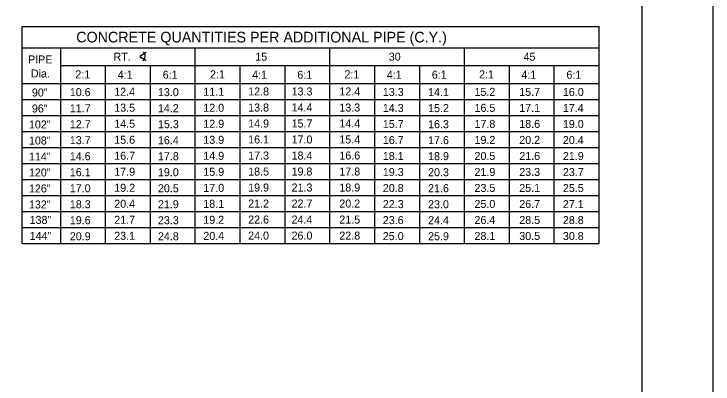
# Model space of a CAD drawing. Extents: x -0.08 to 2.83, y -0.03 to 1.92.
# Drawn here: x 1.811 to 2.833, y 0.542 to 1.083 of the extents above; entities that cross this region are included whole.
import ezdxf

# ---------------------------------------------------------------- set-up
doc = ezdxf.new("R2010")
doc.units = 0
doc.layers.add('57', color=7, linetype='Continuous')
doc.layers.add('63', color=7, linetype='Continuous')

msp = doc.modelspace()

# ---------------------------------------------------------------- linework, layer by layer
at = {"layer": '57'}
for p, q in [((1.8229, 0.7473), (1.8229, 1.065)), ((1.8229, 1.065), (2.6667, 1.065)), ((2.6667, 0.7473), (2.6667, 1.065)), ((1.8229, 1.0338), (2.6667, 1.0338)), ((1.8792, 0.7473), (1.8792, 1.0338)), ((2.076, 0.7473), (2.076, 1.0338)), ((2.2729, 0.7473), (2.2729, 1.0338)), ((2.4698, 0.7473), (2.4698, 1.0338)), ((2.0041, 1.027), (1.9949, 1.0213)), ((1.9949, 1.0213), (2.0041, 1.0151)), ((1.8792, 1.0078), (2.6667, 1.0078)), ((1.9448, 0.7473), (1.9448, 1.0078)), ((2.0104, 0.7473), (2.0104, 1.0078)), ((2.1417, 0.7473), (2.1417, 1.0078)), ((2.2073, 0.7473), (2.2073, 1.0078)), ((2.3386, 0.7473), (2.3386, 1.0078)), ((2.4042, 0.7473), (2.4042, 1.0078)), ((2.5354, 0.7473), (2.5354, 1.0078)), ((2.6011, 0.7473), (2.6011, 1.0078)), ((1.8229, 0.9817), (2.6667, 0.9817)), ((1.8229, 0.9583), (2.6667, 0.9583)), ((2.4697, 0.9583), (2.6667, 0.9583)), ((2.4697, 0.9583), (2.6667, 0.9583)), ((1.8229, 0.9348), (2.6667, 0.9348)), ((2.4697, 0.9348), (2.6667, 0.9348)), ((2.4697, 0.9348), (2.6667, 0.9348)), ((1.8229, 0.9114), (2.6667, 0.9114)), ((2.4697, 0.9114), (2.6667, 0.9114)), ((2.4697, 0.9114), (2.6667, 0.9114)), ((1.8229, 0.888), (2.6667, 0.888)), ((2.4697, 0.888), (2.6667, 0.888)), ((2.4697, 0.888), (2.6667, 0.888)), ((1.8229, 0.8645), (2.6667, 0.8645)), ((2.4697, 0.8645), (2.6667, 0.8645)), ((2.4697, 0.8645), (2.6667, 0.8645)), ((1.8229, 0.8411), (2.6667, 0.8411)), ((2.4697, 0.8411), (2.6667, 0.8411)), ((2.4697, 0.8411), (2.6667, 0.8411)), ((1.8229, 0.8176), (2.6667, 0.8176)), ((2.4697, 0.8176), (2.6667, 0.8176)), ((2.4697, 0.8176), (2.6667, 0.8176)), ((1.8229, 0.7942), (2.6667, 0.7942)), ((2.4697, 0.7942), (2.6667, 0.7942)), ((2.4697, 0.7942), (2.6667, 0.7942)), ((1.8229, 0.7708), (2.6667, 0.7708)), ((2.4697, 0.7708), (2.6667, 0.7708)), ((2.4697, 0.7708), (2.6667, 0.7708)), ((1.8229, 0.7473), (2.6667, 0.7473)), ((2.4697, 0.7473), (2.6667, 0.7473)), ((2.4697, 0.7473), (2.6667, 0.7473))]:
    msp.add_line(p, q, dxfattribs=at)
msp.add_arc((1.9944, 1.0216), 0.00814, 306.1214, 46.4199, dxfattribs=at)
at = {"layer": '63'}
msp.add_line((2.8333, 1.8333), (2.8333, 0), dxfattribs=at)
msp.add_lwpolyline([(0.1667, 0.0624), (0.1667, 1.7708), (2.7292, 1.7708), (2.7292, 0.1041), (2.5625, 0.1041), (2.5625, 0.1458), (2.0739, 0.1458), (2.0739, 0.0624)], close=True, dxfattribs=at)

# ---------------------------------------------------------------- texts
at = {"layer": '57'}
for s, height, p in [('CONCRETE QUANTITIES PER ADDITIONAL PIPE (C.Y.)', 0.015625, (1.9018, 1.0417)), ('PIPE', 0.01171, (1.8313, 1.011)), ('RT.', 0.01171, (1.9563, 1.015)), ('15', 0.01171, (2.1637, 1.015)), ('30', 0.01171, (2.359, 1.015)), ('45', 0.01171, (2.5561, 1.015)), ('Dia.', 0.01171, (1.8354, 0.9904)), ('2:1', 0.0117, (1.9005, 0.9891)), ('2:1', 0.0117, (1.9005, 0.9891)), ('2:1', 0.0117, (1.9005, 0.9891)), ('4:1', 0.0117, (1.9624, 0.9886)), ('4:1', 0.0117, (1.9624, 0.9886)), ('4:1', 0.0117, (1.9624, 0.9886)), ('6:1', 0.0117, (2.0283, 0.9886)), ('6:1', 0.0117, (2.0283, 0.9886)), ('6:1', 0.0117, (2.0283, 0.9886)), ('2:1', 0.0117, (2.0974, 0.9891)), ('2:1', 0.0117, (2.0974, 0.9891)), ('2:1', 0.0117, (2.0974, 0.9891)), ('4:1', 0.0117, (2.1592, 0.9886)), ('4:1', 0.0117, (2.1592, 0.9886)), ('4:1', 0.0117, (2.1592, 0.9886)), ('6:1', 0.0117, (2.2252, 0.9886)), ('6:1', 0.0117, (2.2252, 0.9886)), ('6:1', 0.0117, (2.2252, 0.9886)), ('2:1', 0.0117, (2.2942, 0.9891)), ('2:1', 0.0117, (2.2942, 0.9891)), ('2:1', 0.0117, (2.2942, 0.9891)), ('4:1', 0.0117, (2.3561, 0.9886)), ('4:1', 0.0117, (2.3561, 0.9886)), ('4:1', 0.0117, (2.3561, 0.9886)), ('6:1', 0.0117, (2.422, 0.9886)), ('6:1', 0.0117, (2.422, 0.9886)), ('6:1', 0.0117, (2.422, 0.9886)), ('2:1', 0.0117, (2.4911, 0.9891)), ('2:1', 0.0117, (2.4911, 0.9891)), ('2:1', 0.0117, (2.4911, 0.9891)), ('4:1', 0.0117, (2.553, 0.9886)), ('4:1', 0.0117, (2.553, 0.9886)), ('4:1', 0.0117, (2.553, 0.9886)), ('6:1', 0.0117, (2.6189, 0.9886)), ('6:1', 0.0117, (2.6189, 0.9886)), ('6:1', 0.0117, (2.6189, 0.9886)), (' 90"', 0.0117, (1.8326, 0.9626)), ('10.6', 0.01171, (1.8924, 0.9631)), ('12.4', 0.01171, (1.9574, 0.9637)), ('13.0', 0.01171, (2.0213, 0.9631)), ('11.1', 0.01171, (2.0877, 0.9637)), ('12.8', 0.01171, (2.1533, 0.9641)), ('13.3', 0.01171, (2.2168, 0.9641)), ('12.4', 0.01171, (2.2867, 0.9641)), ('13.3', 0.01171, (2.3503, 0.9633)), ('14.1', 0.01171, (2.4165, 0.9631)), ('15.2', 0.01171, (2.4844, 0.9635)), ('15.7', 0.01171, (2.5499, 0.9635)), ('16.0', 0.01171, (2.6137, 0.9633)), ('11.7', 0.01171, (1.8924, 0.9396)), ('13.5', 0.01171, (1.9574, 0.9403)), ('14.2', 0.01171, (2.0213, 0.9396)), ('12.0', 0.01171, (2.0877, 0.9402)), ('13.8', 0.01171, (2.1533, 0.9406)), ('14.4', 0.01171, (2.2168, 0.9407)), ('13.3', 0.01171, (2.2867, 0.9406)), ('14.3', 0.01171, (2.3503, 0.9399)), ('15.2', 0.01171, (2.4165, 0.9397)), ('16.5', 0.01171, (2.4844, 0.9401)), ('17.1', 0.01171, (2.5499, 0.9401)), ('17.4', 0.01171, (2.6137, 0.9399)), (' 96"', 0.0117, (1.8326, 0.9392)), ('102"', 0.0117, (1.8326, 0.9158)), ('12.7', 0.01171, (1.8924, 0.9162)), ('14.5', 0.01171, (1.9574, 0.9169)), ('15.3', 0.01171, (2.0213, 0.9162)), ('12.9', 0.01171, (2.0877, 0.9168)), ('14.9', 0.01171, (2.1533, 0.9172)), ('15.7', 0.01171, (2.2168, 0.9172)), ('14.4', 0.01171, (2.2867, 0.9172)), ('15.7', 0.01171, (2.3503, 0.9164)), ('16.3', 0.01171, (2.4165, 0.9162)), ('17.8', 0.01171, (2.4844, 0.9166)), ('18.6', 0.01171, (2.5499, 0.9166)), ('19.0', 0.01171, (2.6137, 0.9164)), ('108"', 0.0117, (1.8326, 0.8923)), ('13.7', 0.01171, (1.8924, 0.8928)), ('15.6', 0.01171, (1.9574, 0.8934)), ('16.4', 0.01171, (2.0213, 0.8927)), ('13.9', 0.01171, (2.0877, 0.8933)), ('16.1', 0.01171, (2.1533, 0.8938)), ('17.0', 0.01171, (2.2168, 0.8938)), ('15.4', 0.01171, (2.2867, 0.8938)), ('16.7', 0.01171, (2.3503, 0.893)), ('17.6', 0.01171, (2.4165, 0.8928)), ('19.2', 0.01171, (2.4844, 0.8932)), ('20.2', 0.01171, (2.5499, 0.8932)), ('20.4', 0.01171, (2.6137, 0.893)), ('114"', 0.0117, (1.8326, 0.8689)), ('14.6', 0.01171, (1.8924, 0.8693)), ('16.7', 0.01171, (1.9574, 0.87)), ('17.8', 0.01171, (2.0213, 0.8693)), ('14.9', 0.01171, (2.0877, 0.8699)), ('17.3', 0.01171, (2.1533, 0.8703)), ('18.4', 0.01171, (2.2168, 0.8703)), ('16.6', 0.01171, (2.2867, 0.8703)), ('18.1', 0.01171, (2.3503, 0.8696)), ('18.9', 0.01171, (2.4165, 0.8694)), ('20.5', 0.01171, (2.4844, 0.8697)), ('21.6', 0.01171, (2.5499, 0.8697)), ('21.9', 0.01171, (2.6137, 0.8696)), ('120"', 0.0117, (1.8326, 0.8455)), ('16.1', 0.01171, (1.8924, 0.8459)), ('17.9', 0.01171, (1.9574, 0.8466)), ('19.0', 0.01171, (2.0213, 0.8459)), ('15.9', 0.01171, (2.0877, 0.8465)), ('18.5', 0.01171, (2.1533, 0.8469)), ('19.8', 0.01171, (2.2168, 0.8469)), ('17.8', 0.01171, (2.2867, 0.8469)), ('19.3', 0.01171, (2.3503, 0.8461)), ('20.3', 0.01171, (2.4165, 0.8459)), ('21.9', 0.01171, (2.4844, 0.8463)), ('23.3', 0.01171, (2.5499, 0.8463)), ('23.7', 0.01171, (2.6137, 0.8461)), ('126"', 0.0117, (1.8326, 0.8221)), ('17.0', 0.01171, (1.8924, 0.8224)), ('19.2', 0.01171, (1.9574, 0.8231)), ('20.5', 0.01171, (2.0213, 0.8224)), ('17.0', 0.01171, (2.0877, 0.823)), ('19.9', 0.01171, (2.1533, 0.8235)), ('21.3', 0.01171, (2.2168, 0.8235)), ('18.9', 0.01171, (2.2867, 0.8235)), ('20.8', 0.01171, (2.3503, 0.8227)), ('21.6', 0.01171, (2.4165, 0.8225)), ('23.5', 0.01171, (2.4844, 0.8229)), ('25.1', 0.01171, (2.5499, 0.8229)), ('25.5', 0.01171, (2.6137, 0.8227)), ('132"', 0.0117, (1.8326, 0.7987)), ('18.3', 0.01171, (1.8924, 0.799)), ('20.4', 0.01171, (1.9574, 0.7997)), ('21.9', 0.01171, (2.0213, 0.799)), ('18.1', 0.01171, (2.0877, 0.7996)), ('21.2', 0.01171, (2.1533, 0.8)), ('22.7', 0.01171, (2.2168, 0.8)), ('20.2', 0.01171, (2.2867, 0.8)), ('22.3', 0.01171, (2.3503, 0.7992)), ('23.0', 0.01171, (2.4165, 0.799)), ('25.0', 0.01171, (2.4844, 0.7994)), ('26.7', 0.01171, (2.5499, 0.7994)), ('27.1', 0.01171, (2.6137, 0.7992)), ('138"', 0.0117, (1.8336, 0.7761)), ('19.6', 0.01171, (1.8924, 0.7756)), ('21.7', 0.01171, (1.9574, 0.7762)), ('23.3', 0.01171, (2.0213, 0.7756)), ('19.2', 0.01171, (2.0877, 0.7762)), ('22.6', 0.01171, (2.1533, 0.7766)), ('24.4', 0.01171, (2.2168, 0.7766)), ('21.5', 0.01171, (2.2867, 0.7766)), ('23.6', 0.01171, (2.3503, 0.7758)), ('24.4', 0.01171, (2.4165, 0.7756)), ('26.4', 0.01171, (2.4844, 0.776)), ('28.5', 0.01171, (2.5499, 0.776)), ('28.8', 0.01171, (2.6137, 0.7758)), ('144"', 0.0117, (1.8336, 0.7527)), ('20.9', 0.01171, (1.8924, 0.7521)), ('23.1', 0.01171, (1.9574, 0.7528)), ('24.8', 0.01171, (2.0213, 0.7521)), ('20.4', 0.01171, (2.0877, 0.7527)), ('24.0', 0.01171, (2.1533, 0.7531)), ('26.0', 0.01171, (2.2168, 0.7531)), ('22.8', 0.01171, (2.2867, 0.7531)), ('25.0', 0.01171, (2.3503, 0.7524)), ('25.9', 0.01171, (2.4165, 0.7522)), ('28.1', 0.01171, (2.4844, 0.7526)), ('30.5', 0.01171, (2.5499, 0.7526)), ('30.8', 0.01171, (2.6137, 0.7524))]:
    msp.add_text(s, height=height, dxfattribs=at).set_placement(p)

doc.saveas('drawing.dxf')
